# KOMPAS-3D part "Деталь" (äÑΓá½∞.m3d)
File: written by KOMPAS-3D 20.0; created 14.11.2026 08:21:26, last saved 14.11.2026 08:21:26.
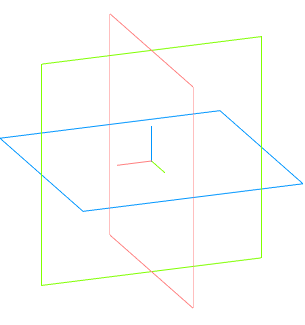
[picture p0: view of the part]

Document properties: Полное имя файла: D:\myProjects\Progect_esp32\box_compas\сборки компонентов\Деталь.m3d

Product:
- Part/product: Деталь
